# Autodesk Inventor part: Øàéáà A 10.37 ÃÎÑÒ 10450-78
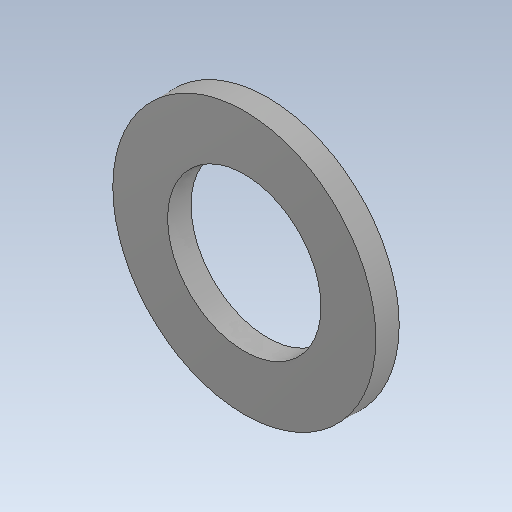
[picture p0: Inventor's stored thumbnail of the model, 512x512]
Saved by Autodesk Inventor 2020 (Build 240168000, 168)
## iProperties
Created: 1900-01
Part Number: Øàéáà A 10.37 ÃÎÑÒ 10450-78
Material: Générique
Document SubType Name: Modeling
Designer: bruno
Density: 1 g/cm^3
Appearance: Par défaut
Author: bruno
Revision Number: ANYUNSPECIFIED
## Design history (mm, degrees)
feature "Base1"
node "Solide1"
